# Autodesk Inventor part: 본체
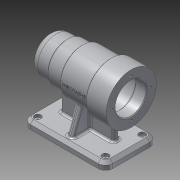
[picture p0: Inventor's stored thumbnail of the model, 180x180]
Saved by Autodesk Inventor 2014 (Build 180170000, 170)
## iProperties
Created: 2016-06
Part Number: 본체
Material: Aluminum 6061
Document SubType Name: Modeling
Designer: 601-
Density: 2.71 g/cm^3
Appearance: Aluminum - Flat
Mass: 672.406 g
Surface Area: 650.211 cm^2
Volume: 248.12 cm^3
Author: 601-
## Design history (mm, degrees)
sketch "Sketch1"
  geometry: L1 (0, 0)-(0, 25); L2 (0, 25)-(25, 25); L3 (25, 25)-(25, 27); L4 (25, 27)-(45, 27); L5 (45, 27)-(45, 30); L6 (45, 30)-(84, 30); L7 (84, 30)-(84, 34); L8 (84, 34)-(112, 34); L9 (112, 34)-(112, 0); L10 (112, 0)-(0, 0)
  constraints: 20 end point, 6 parallel, 3 perpendicular, 1 vertical
  dimensions: "d0" = 25 distance between parallel lines of L3 L1; "d1" = 45 distance between parallel lines of L5 L1; "d2" = 84 distance between parallel lines of L7 L1; "d3" = 112 distance between parallel lines of L9 L1; "d4" = 68 diameter of L8 L10; "d5" = 60 diameter of L6 L10; "d6" = 54 diameter of L4 L10; "d7" = 50 diameter of L2 L10
revolve "Revolution1" sketch "Sketch1" stored, may be unused: angle "d8" = 90 deg
workplane "Work Plane1"
sketch "Sketch2"
  geometry: L1 (0, 35)-(112, 35); L2 (112, 35)-(112, -35); L3 (112, -35)-(0, -35); L4 (0, -35)-(0, 35); 2 further points
  constraints: 8 end point, 2 parallel, 1 coincident, 1 horizontal, 1 midpoint, 1 perpendicular
  dimensions: "d10" = 112 distance of L1.start L1.end; "d11" = 70 distance of L3.end L1.start
extrude "Extrusion1" join sketch "Sketch2" distance "d12" = 10; taper "d13" = 0 deg
sketch "Sketch3"
  geometry: L1 (-112, -60)-(0, -60) reference; L2 (-20, -25)-(-20, -60); L3 (0, -70)-(0, -60) reference; L4 (-112, -70)-(-112, -60) reference; L5 (-92, -34)-(-92, -60); L6 (0, -25)-(-25, -25) reference; L7 (-84, -34)-(-112, -34) reference; L8 (-20, -25)-(-44.839, -13.339); L9 (-44.839, -13.339)-(-81.221, -16.559); L10 (-81.221, -16.559)-(-92, -22.193); L11 (-92, -22.193)-(-92, -34); L12 (-92, -60)-(-20, -60); 1 further point
  constraints: 14 end point, 4 point on line, 3 perpendicular, 1 collinear
  dimensions: "d14" = 20 distance between parallel lines of L2 L3; "d15" = 20 distance between parallel lines of L5 L4
extrude "Extrusion2" join sketch "Sketch3" stored distance "d16" = 8; taper "d17" = 0 deg
workplane "Work Plane2"
sketch "Sketch4"
  geometry: L1 (-70, -35)-(-60, -35) reference; L2 (-70, 35)-(-60, 35) reference; L3 (-60, -35)-(-60, 35) reference; L4 (-60, -28)-(-25.68, -15.509); L5 (0, 0)-(-60, 0); L6 (-60, 28)-(-25.68, 15.509); L7 (-60, 28)-(-60, -28); L8 (-25.68, 15.509)-(-25.68, -15.509); A1 r 30 centre (0, 0) between (-29.732, -4) and (-29.732, 4) reference; 1 further point
  constraints: 10 end point, 2 symmetric about line, 1 collinear, 1 midpoint, 1 parallel, 1 point on circle, 1 point on line
  dimensions: "d18" = 7 distance from line of L1 L4.start; "d19" = 110 deg angle of L4 L3
extrude "Extrusion3" join sketch "Sketch4" stored distance "d20" = 8; taper "d21" = 0 deg
fillet "Fillet1" dims "d22" = 10
sketch "Sketch5"
  geometry: L1 (-6, 0)-(-6, 10.5); L2 (-6, 10.5)-(-9, 10.5); L3 (-9, 10.5)-(-9, 16); L4 (-9, 16)-(-13, 16); L5 (-13, 16)-(-13, 17.5); L6 (-13, 17.5)-(-31, 17.5); L7 (-31, 17.5)-(-31, 21); L8 (-31, 21)-(-43, 21); L9 (-43, 21)-(-43, 24); L10 (-43, 24)-(-97, 24); L11 (-97, 24)-(-97, 21); L12 (-112, 34)-(-112, -34) reference; L13 (-97, 21)-(-112, 21); L14 (-112, 21)-(-112, 0); L15 (-112, 0)-(-6, 0); 1 further point
  constraints: 28 end point, 9 parallel, 3 perpendicular, 1 midpoint, 1 point on line, 1 vertical
  dimensions: "d23" = 48 diameter of L10 L15; "d24" = 42 diameter of L13 L15; "d25" = 42 diameter of L8 L15; "d26" = 35 diameter of L6 L15; "d27" = 32 diameter of L4 L15; "d28" = 21 diameter of L2 L15; "d29" = 3 distance between parallel lines of L3 L1; "d30" = 4 distance between parallel lines of L5 L3; "d31" = 18 distance between parallel lines of L7 L5; "d32" = 12 distance between parallel lines of L9 L7; "d33" = 15 distance between parallel lines of L14 L11; "d34" = 54 distance between parallel lines of L11 L9
revolve "Revolution2" sketch "Sketch5" stored, may be unused: angle "d35" = 90 deg
sketch "Sketch6" dims "d36" = 52
  geometry: L1 (0, 0)-(-26, 0); 3 further points
  constraints: 3 coincident, 2 end point, 1 horizontal, 1 horizontal alignment, 2 other
hole "Hole1" sketch "Sketch6" at (-26, 0) diameter "d37" = 3.242; stored, may be unused: countersink angle "d41" = 90 deg, drill point angle "d43" = 118 deg; dims "d38" = 8, "d39" = 4, "d40" = 2, "d42" = 11
pattern_circular "Circular Pattern1" dims angle "d45" = 360 deg
fillet "Fillet2" dims "d47" = 10
sketch "Sketch7"
  geometry: L1 (102, -35)-(10, -35) reference; L2 (0, -25)-(0, 25) reference; L3 (10, 35)-(102, 35) reference; L4 (112, 25)-(112, -25) reference; 5 further points
  dimensions: "d48" = 92 distance of point (102, 25) point (10, 25); "d49" = 50 distance of point (10, -25) point (10, 25); "d50" = 10 distance from line of L1 point (10, -25); "d51" = 10 distance from line of point (10, -25) L2; "d52" = 10 distance from line of L2 point (10, 25); "d53" = 10 distance from line of point (10, 25) L3 (derived); "d54" = 10 distance from line of L3 point (102, 25); "d55" = 10 distance from line of L4 point (102, -25); "d56" = 10 distance from line of L1 point (102, -25)
hole "Hole2" sketch "Sketch7" at (10, 25), (102, 25), (102, -25), (10, -25) diameter "d57" = 5; stored, may be unused: countersink angle "d61" = 90 deg, drill point angle "d63" = 118 deg; dims "d58" = 8, "d59" = 9, "d60" = 4, "d62" = 11
chamfer "Chamfer1" distance "d64" = 4; stored, may be unused: second distance "d65" = 2, angle "d66" = 45 deg
chamfer "Chamfer2" distance "d67" = 1; stored, may be unused: second distance "d68" = 2, angle "d69" = 45 deg
chamfer "Chamfer3" distance "d70" = 1; stored, may be unused: second distance "d71" = 2, angle "d72" = 45 deg
fillet "Fillet3" dims "d73" = 3
fillet "Fillet4" dims "d74" = 0.3
fillet "Fillet5" dims "d75" = 3
fillet "Fillet6" dims "d76" = 3
fillet "Fillet7" dims "d77" = 3
fillet "Fillet8" dims "d78" = 3
fillet "Fillet9" dims "d79" = 3
workplane "Work Plane6"
  workplane "Work Plane5"
sketch "Sketch10"
  geometry: L1 (-16.092, 2.402)-(17.092, 2.402); L2 (17.092, 2.402)-(17.092, -2.402); L3 (17.092, -2.402)-(-16.092, -2.402); L4 (-16.092, -2.402)-(-16.092, 2.402); L5 (-16.092, 0)-(17.092, 0); L6 (0.5, 2.402)-(0.5, -2.402); L7 (-47.5, 34)-(-47.5, -34) reference; 3 further points
  constraints: 6 midpoint, 4 end point, 1 horizontal alignment, 2 other
  dimensions: "d81" = 48 distance from line of L7 point (0.5, 0)
extrude "Extrusion4" join sketch "Sketch10" distance "d82" = 0.5; taper "d83" = 0 deg
body "Solid1"
